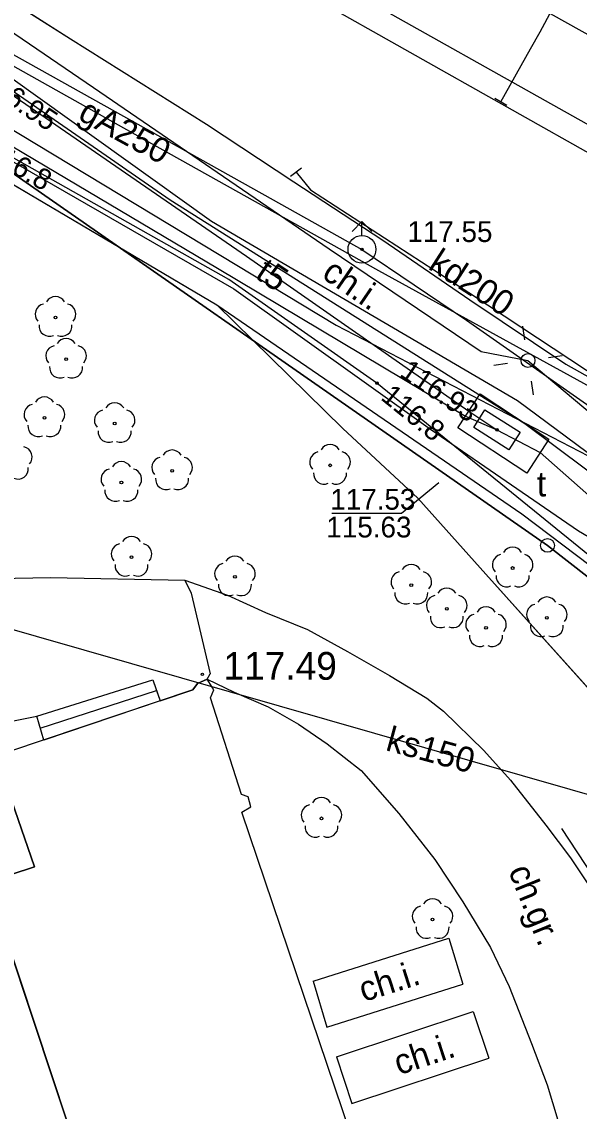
# Model space of a CAD drawing. Extents: x 6434771 to 6436222, y 5663454 to 5664782.
# Drawn here: x 6435031.8 to 6435051.9, y 5663965.39 to 5664004.67 of the extents above; entities that cross this region are included whole.
import ezdxf

# ---------------------------------------------------------------- set-up
doc = ezdxf.new("R2010")
doc.units = 0
for name, color, linetype in [('Warstwa 1', 7, 'Continuous'), ('Warstwa 10', 7, 'Continuous'), ('Warstwa 11', 7, 'Continuous'), ('Warstwa 12', 7, 'Continuous'), ('Warstwa 13', 7, 'Continuous'), ('Warstwa 14', 7, 'Continuous'), ('Warstwa 15', 7, 'Continuous'), ('Warstwa 2', 7, 'Continuous'), ('Warstwa 20', 7, 'Continuous'), ('Warstwa 25', 7, 'Continuous'), ('Warstwa 36', 7, 'Continuous'), ('Warstwa 37', 7, 'Continuous'), ('Warstwa 4', 7, 'Continuous'), ('Warstwa 5', 7, 'Continuous'), ('Warstwa 6', 7, 'Continuous'), ('Warstwa 7', 7, 'Continuous'), ('Warstwa 8', 7, 'Continuous'), ('Warstwa 9', 7, 'Continuous')]:
    doc.layers.add(name, color=color, linetype=linetype)

msp = doc.modelspace()

# ---------------------------------------------------------------- linework, layer by layer
at = {"layer": 'Warstwa 1'}
for p, q in [((6435026.957, 5664002.35), (6435050.759, 5663985.791)), ((6435026.957, 5664002.35), (6435050.759, 5663985.791)), ((6435050.759, 5663985.791), (6435055.831, 5663981.839)), ((6435050.759, 5663985.791), (6435055.831, 5663981.839))]:
    msp.add_line(p, q, dxfattribs=at)
for points in [[(6435045.895, 5663957.98), (6435039.739, 5663976.169), (6435040.058, 5663976.363), (6435039.962, 5663976.729), (6435039.728, 5663976.813), (6435038.605, 5663980.3), (6435038.722, 5663980.588), (6435038.493, 5663980.968), (6435038.135, 5663980.806), (6435037.976, 5663980.581), (6435031.321, 5663978.344)], [(6435030.834, 5663978.315), (6435032.261, 5663974.203), (6435030.566, 5663973.645), (6435039.149, 5663947.769)]]:
    msp.add_lwpolyline(points, dxfattribs=at)
at = {"layer": 'Warstwa 10'}
for points in [[(6434898.671, 5664074.419), (6434902.76, 5664072.365), (6434912.576, 5664067.627), (6434922.039, 5664062.843), (6434928.491, 5664059.745), (6434937.421, 5664055.317), (6434945.409, 5664050.998), (6434960.407, 5664042.783), (6434962.523, 5664038.882), (6434979.882, 5664029.167), (6434995.86, 5664020.139), (6435019.103, 5664006.754), (6435039.449, 5663995.035), (6435046.546, 5663989.977), (6435049.657, 5663987.84), (6435051.881, 5663986.317), (6435053.049, 5663985.633), (6435057.374, 5663981.038), (6435060.712, 5663977.517), (6435062.186, 5663975.788), (6435062.844, 5663975.005)], [(6434896.42, 5664071.06), (6434898.16, 5664073.03), (6434900.23, 5664072.06), (6434923.31, 5664061.23), (6434926.55, 5664059.81), (6434927.25, 5664060), (6434930.24, 5664058.57), (6434930.73, 5664057.88), (6434948.57, 5664048.49), (6434986.66, 5664027.63), (6435008.6, 5664015.27), (6435029.24, 5664003.72), (6435037.15, 5663998.25), (6435049.94, 5663990.19), (6435056.65, 5663985.18), (6435065.79, 5663976.31), (6435067.86, 5663972.11), (6435071.01, 5663962.36), (6435072.82, 5663959.6), (6435082.35, 5663954.64), (6435097.639, 5663946.244)], [(6435029.359, 5664004.111), (6435038.639, 5663997.479), (6435049.682, 5663991.014), (6435059.257, 5663983.908), (6435063.578, 5663979.846), (6435066.7, 5663975.848), (6435068.234, 5663972.039), (6435070.123, 5663963.685), (6435072.703, 5663960.364), (6435083.097, 5663954.788), (6435088.923, 5663951.177), (6435095.392, 5663948.519), (6435099.449, 5663946.22)], [(6435099.552, 5663946.221), (6435098.33, 5663946.9), (6435093.95, 5663949.47), (6435091.03, 5663950.32), (6435083.09, 5663955.03), (6435073.14, 5663960.81), (6435072.01, 5663961.77), (6435069.49, 5663965.07), (6435065.5, 5663971.7), (6435061.58, 5663976.4), (6435056.94, 5663981.63), (6435044.61, 5663991.64), (6435039.27, 5663995.38), (6435030.2, 5664000.49)]]:
    msp.add_lwpolyline(points, dxfattribs=at)
msp.add_circle((6435050.759, 5663985.791), 0.25, dxfattribs=at)
msp.add_circle((6435050.759, 5663985.791), 0.25, dxfattribs=at)
at = {"layer": 'Warstwa 11'}
for centre in [(6435033.018, 5663994.01), (6435033.4, 5663992.504), (6435032.618, 5663990.392), (6435035.152, 5663990.185), (6435037.222, 5663988.481), (6435042.919, 5663988.677), (6435035.393, 5663988.061), (6435035.76, 5663985.363), (6435049.503, 5663984.975), (6435039.489, 5663984.655), (6435045.848, 5663984.357), (6435047.128, 5663983.502), (6435048.543, 5663982.822), (6435050.737, 5663983.181), (6435042.609, 5663975.949), (6435046.615, 5663972.301)]:
    msp.add_circle(centre, 0.05, dxfattribs=at)
for centre, start, end in [((6435033.018, 5663994.385), 30.1471, 149.8529), ((6435032.661, 5663994.126), 102.1471, 221.8529), ((6435033.375, 5663994.126), 318.1471, 77.8529), ((6435032.798, 5663993.707), 174.1471, 293.8529), ((6435033.238, 5663993.707), 246.1471, 5.8529), ((6435033.4, 5663992.879), 30.1471, 149.8529), ((6435033.043, 5663992.62), 102.1471, 221.8529), ((6435033.757, 5663992.62), 318.1471, 77.8529), ((6435033.18, 5663992.201), 174.1471, 293.8529), ((6435033.62, 5663992.201), 246.1471, 5.8529), ((6435032.618, 5663990.767), 30.1471, 149.8529), ((6435032.261, 5663990.508), 102.1471, 221.8529), ((6435032.975, 5663990.508), 318.1471, 77.8529), ((6435035.152, 5663990.56), 30.1471, 149.8529), ((6435034.795, 5663990.301), 102.1471, 221.8529), ((6435035.509, 5663990.301), 318.1471, 77.8529), ((6435032.398, 5663990.089), 174.1471, 293.8529), ((6435032.838, 5663990.089), 246.1471, 5.8529), ((6435034.932, 5663989.882), 174.1471, 293.8529), ((6435035.372, 5663989.882), 246.1471, 5.8529), ((6435031.8, 5663988.976), 318.1471, 77.8529), ((6435037.222, 5663988.856), 30.1471, 149.8529), ((6435042.562, 5663988.793), 102.1471, 221.8529), ((6435042.919, 5663989.052), 30.1471, 149.8529), ((6435043.276, 5663988.793), 318.1471, 77.8529), ((6435035.393, 5663988.436), 30.1471, 149.8529), ((6435036.865, 5663988.597), 102.1471, 221.8529), ((6435037.579, 5663988.597), 318.1471, 77.8529), ((6435031.663, 5663988.557), 246.1471, 5.8529), ((6435035.036, 5663988.177), 102.1471, 221.8529), ((6435035.75, 5663988.177), 318.1471, 77.8529), ((6435042.699, 5663988.374), 174.1471, 293.8529), ((6435043.139, 5663988.374), 246.1471, 5.8529), ((6435037.002, 5663988.178), 174.1471, 293.8529), ((6435037.442, 5663988.178), 246.1471, 5.8529), ((6435035.173, 5663987.758), 174.1471, 293.8529), ((6435035.613, 5663987.758), 246.1471, 5.8529), ((6435035.76, 5663985.738), 30.1471, 149.8529), ((6435035.403, 5663985.479), 102.1471, 221.8529), ((6435036.117, 5663985.479), 318.1471, 77.8529), ((6435049.503, 5663985.35), 30.1471, 149.8529), ((6435039.489, 5663985.03), 30.1471, 149.8529), ((6435049.146, 5663985.091), 102.1471, 221.8529), ((6435049.86, 5663985.091), 318.1471, 77.8529), ((6435035.54, 5663985.06), 174.1471, 293.8529), ((6435035.98, 5663985.06), 246.1471, 5.8529), ((6435039.132, 5663984.771), 102.1471, 221.8529), ((6435039.846, 5663984.771), 318.1471, 77.8529), ((6435045.491, 5663984.473), 102.1471, 221.8529), ((6435045.848, 5663984.732), 30.1471, 149.8529), ((6435046.205, 5663984.473), 318.1471, 77.8529), ((6435049.283, 5663984.672), 174.1471, 293.8529), ((6435049.723, 5663984.672), 246.1471, 5.8529), ((6435039.269, 5663984.352), 174.1471, 293.8529), ((6435039.709, 5663984.352), 246.1471, 5.8529), ((6435045.628, 5663984.054), 174.1471, 293.8529), ((6435046.068, 5663984.054), 246.1471, 5.8529), ((6435047.128, 5663983.877), 30.1471, 149.8529), ((6435046.771, 5663983.618), 102.1471, 221.8529), ((6435047.485, 5663983.618), 318.1471, 77.8529), ((6435050.38, 5663983.297), 102.1471, 221.8529), ((6435050.737, 5663983.556), 30.1471, 149.8529), ((6435051.094, 5663983.297), 318.1471, 77.8529), ((6435048.186, 5663982.938), 102.1471, 221.8529), ((6435048.543, 5663983.197), 30.1471, 149.8529), ((6435048.9, 5663982.938), 318.1471, 77.8529), ((6435046.908, 5663983.199), 174.1471, 293.8529), ((6435047.348, 5663983.199), 246.1471, 5.8529), ((6435050.517, 5663982.878), 174.1471, 293.8529), ((6435050.957, 5663982.878), 246.1471, 5.8529), ((6435048.323, 5663982.519), 174.1471, 293.8529), ((6435048.763, 5663982.519), 246.1471, 5.8529), ((6435042.609, 5663976.324), 30.1471, 149.8529), ((6435042.252, 5663976.065), 102.1471, 221.8529), ((6435042.966, 5663976.065), 318.1471, 77.8529), ((6435042.389, 5663975.646), 174.1471, 293.8529), ((6435042.829, 5663975.646), 246.1471, 5.8529), ((6435046.615, 5663972.676), 30.1471, 149.8529), ((6435046.258, 5663972.417), 102.1471, 221.8529), ((6435046.972, 5663972.417), 318.1471, 77.8529), ((6435046.395, 5663971.998), 174.1471, 293.8529), ((6435046.835, 5663971.998), 246.1471, 5.8529)]:
    msp.add_arc(centre, 0.375, start, end, dxfattribs=at)
at = {"layer": 'Warstwa 12'}
for points in [[(6434879.158, 5664078.856), (6434884.466, 5664077.041), (6434884.943, 5664076.892), (6434885.361, 5664076.61), (6434904.643, 5664068.316), (6434925.269, 5664058.705), (6434945.05, 5664048.685), (6434974.567, 5664032.476), (6434974.989, 5664032.261), (6434975.127, 5664032.48), (6434976.891, 5664035.328), (6434977.019, 5664035.547), (6434977.471, 5664035.311), (6435021.423, 5664010.318), (6435021.865, 5664010.097), (6435021.856, 5664009.772), (6435020.661, 5664007.687), (6435020.508, 5664007.434), (6435020.935, 5664007.143), (6435043.134, 5663993.734), (6435056.442, 5663986.832), (6435065.286, 5663979.645), (6435065.567, 5663979.291)], [(6435076.981, 5663977.987), (6435060.8, 5663986.83), (6435044.672, 5663995.689), (6435035.779, 5664000.664), (6435026.559, 5664005.848), (6435021.216, 5664008.862), (6435015.543, 5664011.986), (6435005.727, 5664017.515), (6434993.895, 5664024.292), (6434988.15, 5664027.391), (6434986.652, 5664028.144), (6434985.953, 5664028.56), (6434978.495, 5664032.512), (6434971.253, 5664036.441), (6434966.665, 5664038.927), (6434949.941, 5664048.002), (6434948.145, 5664048.942), (6434947.222, 5664049.507), (6434943.986, 5664051.256), (6434934.8, 5664055.982), (6434925.516, 5664060.59), (6434905.925, 5664069.826), (6434896.606, 5664074.336), (6434894.752, 5664075.227)], [(6434928.096, 5664058.264), (6434929.076, 5664057.604), (6434939.486, 5664051.98), (6434948.125, 5664047.34), (6434952.325, 5664045.068), (6434966.421, 5664037.465), (6434988.007, 5664025.883), (6434989.76, 5664024.876), (6434992.028, 5664023.706), (6434998.449, 5664019.821), (6435020.142, 5664006.907), (6435038.86, 5663995.783), (6435047.805, 5663990.452), (6435048.936, 5663989.958)], [(6434986.93, 5664031.717), (6434992.77, 5664028.437), (6435004.492, 5664021.894), (6435005.105, 5664018.185), (6435011.542, 5664014.684), (6435027.829, 5664005.549), (6435040.87, 5663998.248), (6435044.067, 5663996.463), (6435047.835, 5663993.916), (6435060.611, 5663984.964), (6435069.684, 5663978.472), (6435072.37, 5663972.912), (6435073.728, 5663967.815), (6435073.844, 5663967.084), (6435073.839, 5663962.379), (6435073.912, 5663958.232), (6435075.469, 5663957.501), (6435076.211, 5663957.1), (6435093.406, 5663947.233)], [(6434990.077, 5664025.283), (6434990.843, 5664024.793), (6434996.581, 5664021.557), (6435010.751, 5664013.657), (6435028.787, 5664003.637), (6435029.346, 5664003.299), (6435029.924, 5664003.079), (6435039.903, 5663996.215), (6435047.922, 5663990.632), (6435048.936, 5663989.958)], [(6435029.763, 5664005.454), (6435034.388, 5664002.299), (6435042.886, 5663996.481), (6435048.366, 5663992.784), (6435050.056, 5663992.458), (6435053.785, 5663989.318), (6435060.963, 5663983.658), (6435062.158, 5663982.516), (6435067.739, 5663976.436), (6435069.698, 5663972.561), (6435070.863, 5663972.195), (6435071.455, 5663970.037), (6435072.977, 5663964.049), (6435072.957, 5663962.572), (6435082.449, 5663958.039), (6435089.417, 5663954.626), (6435090.354, 5663954.835), (6435092.145, 5663953.831), (6435102.441, 5663948.316), (6435106.279, 5663946.137)], [(6435048.936, 5663989.958), (6435050.494, 5663989.135), (6435059.853, 5663980.868), (6435060.69, 5663980.006)]]:
    msp.add_lwpolyline(points, dxfattribs=at)
at = {"layer": 'Warstwa 14'}
msp.add_lwpolyline([(6435042.984, 5663986.953), (6435045.497, 5663986.953), (6435046.843, 5663988.054)], dxfattribs=at)
for centre in [(6435044.61, 5663991.64), (6435048.936, 5663989.958), (6435048.936, 5663989.958)]:
    msp.add_circle(centre, 0.045, dxfattribs=at)
at = {"layer": 'Warstwa 15'}
msp.add_lwpolyline([(6435047.527, 5663990.027), (6435048.327, 5663991.25), (6435050.813, 5663989.623), (6435050.013, 5663988.4)], close=True, dxfattribs=at)
at = {"layer": 'Warstwa 2'}
for points in [[(6434997.74, 5664018.73), (6434999.49, 5664017.72), (6435038.83, 5663994.46)], [(6435038.83, 5663994.46), (6435043.374, 5663990.006), (6435046.081, 5663987.498), (6435048.536, 5663984.758)], [(6435072.736, 5663952.323), (6435067.928, 5663955.002), (6435067.798, 5663959.143), (6435063.036, 5663968.152), (6435059.834, 5663972.111), (6435056.391, 5663976.002), (6435048.536, 5663984.758)], [(6435031.791, 5663948.063), (6435032.526, 5663945.742), (6435032.791, 5663945.495), (6435036.28, 5663946.559), (6435036.993, 5663946.976), (6435039.149, 5663947.769), (6435035.704, 5663958.157), (6435033.205, 5663965.69), (6435031.909, 5663969.598), (6435030.566, 5663973.645), (6435032.261, 5663974.203), (6435030.834, 5663978.315)]]:
    msp.add_lwpolyline(points, dxfattribs=at)
msp.add_circle((6435050.056, 5663992.458), 0.25, dxfattribs=at)
at = {"layer": 'Warstwa 20'}
for p, q in [((6435049.288, 5664001.652), (6435048.856, 5664001.902)), ((6435041.493, 5663999.098), (6435041.889, 5663999.404))]:
    msp.add_line(p, q, dxfattribs=at)
at = {"layer": 'Warstwa 25'}
msp.add_circle((6435038.314, 5663981.14), 0.045, dxfattribs=at)
at = {"layer": 'Warstwa 36'}
msp.add_line((6435032.47, 5663979.205), (6435036.664, 5663980.564), dxfattribs=at)
msp.add_lwpolyline([(6435032.592, 5663978.772), (6435032.35, 5663979.64), (6435036.531, 5663980.942), (6435036.798, 5663980.185)], close=True, dxfattribs=at)
at = {"layer": 'Warstwa 37'}
for points in [[(6434960.077, 5664056.173), (6434990.448, 5664038.674), (6435077.587, 5663990.05), (6435102.909, 5663975.479)], [(6435101.756, 5663972.773), (6435075.965, 5663987.638), (6434996.783, 5664032.063), (6434958.785, 5664053.528)]]:
    msp.add_lwpolyline(points, dxfattribs=at)
at = {"layer": 'Warstwa 4'}
for points in [[(6435043.713, 5663997.109), (6435044.067, 5663997.463)], [(6435044.421, 5663997.109), (6435044.067, 5663997.463)], [(6435044.067, 5663996.963), (6435044.067, 5663997.463)], [(6435049.945, 5663993.2), (6435049.872, 5663993.694)], [(6435049.314, 5663992.347), (6435048.82, 5663992.274)], [(6435050.798, 5663992.569), (6435051.292, 5663992.642)], [(6435050.167, 5663991.716), (6435050.24, 5663991.222)], [(6435061.004, 5663948.939), (6435060.419, 5663957.687), (6435058.856, 5663963.156), (6435055.243, 5663969.55), (6435051.275, 5663975.588)]]:
    msp.add_lwpolyline(points, dxfattribs=at)
msp.add_lwpolyline([(6435048.102, 5663990.043), (6435048.504, 5663990.677), (6435049.77, 5663989.873), (6435049.368, 5663989.239)], close=True, dxfattribs=at)
msp.add_circle((6435044.067, 5663996.463), 0.5, dxfattribs=at)
at = {"layer": 'Warstwa 5'}
for p, q in [((6434999.49, 5664017.72), (6435038.83, 5663994.46)), ((6435038.83, 5663994.46), (6435043.374, 5663990.006)), ((6435038.83, 5663994.46), (6435049.833, 5663986.932)), ((6435038.83, 5663994.46), (6435043.374, 5663990.006)), ((6435043.374, 5663990.006), (6435046.081, 5663987.498)), ((6435043.374, 5663990.006), (6435046.081, 5663987.498)), ((6435046.081, 5663987.498), (6435048.536, 5663984.758)), ((6435046.081, 5663987.498), (6435048.536, 5663984.758)), ((6435049.833, 5663986.932), (6435053.836, 5663983.904)), ((6435030.14, 5663984.577), (6435032.835, 5663984.632)), ((6435032.835, 5663984.632), (6435037.682, 5663984.542)), ((6435037.682, 5663984.542), (6435039.218, 5663983.992)), ((6435048.536, 5663984.758), (6435056.391, 5663976.002)), ((6435048.536, 5663984.758), (6435056.391, 5663976.002)), ((6435039.218, 5663983.992), (6435040.596, 5663983.376)), ((6435040.596, 5663983.376), (6435042.108, 5663982.759)), ((6435042.108, 5663982.759), (6435043.551, 5663981.964)), ((6435043.551, 5663981.964), (6435045.061, 5663981.103)), ((6435045.061, 5663981.103), (6435046.414, 5663980.287)), ((6435046.414, 5663980.287), (6435047.011, 5663979.814)), ((6435047.011, 5663979.814), (6435048.458, 5663978.4)), ((6435048.458, 5663978.4), (6435049.428, 5663977.322)), ((6435049.428, 5663977.322), (6435050.705, 5663975.709)), ((6435050.705, 5663975.709), (6435051.584, 5663974.523)), ((6435051.584, 5663974.523), (6435053.067, 5663972.307))]:
    msp.add_line(p, q, dxfattribs=at)
at = {"layer": 'Warstwa 6'}
for points in [[(6435199.169, 5663878.85), (6435069.683, 5663952.11), (6435070.435, 5663958.091), (6435069.483, 5663961.233), (6435068.325, 5663963.837), (6435062.043, 5663974.514), (6435058.095, 5663979.622), (6435055.831, 5663981.839), (6435050.759, 5663985.791), (6435026.957, 5664002.35), (6434999.334, 5664017.996), (6434991.09, 5664022.666), (6434980.58, 5664028.593), (6434951.952, 5664044.671), (6434942.859, 5664049.431), (6434933.864, 5664054.041), (6434925.132, 5664058.117), (6434918.181, 5664061.441), (6434909.328, 5664065.359), (6434902.911, 5664068.147), (6434896.533, 5664070.874)], [(6435027.108, 5664008.168), (6435033.554, 5664004.049), (6435038.461, 5664000.982), (6435041.615, 5663998.897), (6435044.819, 5663996.801), (6435047.954, 5663994.645), (6435051.422, 5663992.324), (6435054.269, 5663990.729)]]:
    msp.add_lwpolyline(points, dxfattribs=at)
msp.add_lwpolyline([(6435026.957, 5664002.35), (6435050.759, 5663985.791), (6435055.831, 5663981.839), (6435058.095, 5663979.622), (6435062.043, 5663974.514), (6435068.325, 5663963.837), (6435069.483, 5663961.233), (6435070.435, 5663958.091), (6435069.683, 5663952.11), (6435120.043, 5663983.972), (6435070.884, 5664005.038), (6435011.285, 5664038.642), (6434957.736, 5664068.872), (6434942.859, 5664049.431), (6434951.952, 5664044.671), (6434980.58, 5664028.593), (6434991.09, 5664022.666), (6434999.334, 5664017.996)], close=True, dxfattribs=at)
for centre in [(6435044.067, 5663996.463), (6435048.936, 5663989.958)]:
    msp.add_circle(centre, 0.045, dxfattribs=at)
at = {"layer": 'Warstwa 7'}
for points in [[(6434960.516, 5664035.877), (6434960.352, 5664035.549), (6434973.215, 5664023.743), (6434973.286, 5664023.312), (6434995.263, 5664004.719), (6434995.671, 5664004.448), (6435025.261, 5663984.54), (6435077.854, 5663969.472)], [(6435049.072, 5664001.777), (6435050.141, 5664003.69), (6435050.499, 5664004.312), (6435051.281, 5664005.776), (6435051.511, 5664006.218), (6435055.779, 5664004.771), (6435056.167, 5664004.607), (6435056.821, 5664004.929), (6435057.95, 5664005.645), (6435058.494, 5664005.989)], [(6435041.691, 5663999.251), (6435042.211, 5663998.615), (6435047.994, 5663994.861), (6435058.743, 5663987.769), (6435059.445, 5663987.461), (6435061.77, 5663989.977), (6435070.529, 5663999.495)]]:
    msp.add_lwpolyline(points, dxfattribs=at)
at = {"layer": 'Warstwa 8'}
for p, q in [((6434997.36, 5664030.89), (6435055.68, 5663998)), ((6434997.36, 5664030.89), (6435055.68, 5663998)), ((6435027.108, 5664008.168), (6435033.554, 5664004.049)), ((6435033.554, 5664004.049), (6435038.461, 5664000.982)), ((6435038.461, 5664000.982), (6435041.615, 5663998.897)), ((6435041.615, 5663998.897), (6435044.819, 5663996.801)), ((6435044.819, 5663996.801), (6435047.954, 5663994.645)), ((6435047.954, 5663994.645), (6435051.422, 5663992.324)), ((6435051.422, 5663992.324), (6435054.269, 5663990.729)), ((6435030.14, 5663984.577), (6435032.835, 5663984.632)), ((6435032.835, 5663984.632), (6435037.682, 5663984.542)), ((6435037.682, 5663984.542), (6435037.915, 5663984.063)), ((6435037.915, 5663984.063), (6435038.359, 5663982.177)), ((6435038.359, 5663982.177), (6435038.592, 5663981.158)), ((6435032.35, 5663979.64), (6435036.531, 5663980.942)), ((6435036.531, 5663980.942), (6435036.664, 5663980.564)), ((6435038.135, 5663980.806), (6435038.493, 5663980.968)), ((6435038.493, 5663980.968), (6435038.592, 5663981.158)), ((6435036.664, 5663980.564), (6435036.798, 5663980.185)), ((6435036.798, 5663980.185), (6435037.976, 5663980.581)), ((6435037.976, 5663980.581), (6435038.135, 5663980.806)), ((6435031.447, 5663979.454), (6435032.35, 5663979.64))]:
    msp.add_line(p, q, dxfattribs=at)
at = {"layer": 'Warstwa 9'}
for p, q in [((6434999.49, 5664017.72), (6435038.83, 5663994.46)), ((6435027.108, 5664008.168), (6435033.554, 5664004.049)), ((6435033.554, 5664004.049), (6435038.461, 5664000.982)), ((6435038.461, 5664000.982), (6435041.615, 5663998.897)), ((6435041.615, 5663998.897), (6435044.819, 5663996.801)), ((6435044.819, 5663996.801), (6435047.954, 5663994.645)), ((6435038.83, 5663994.46), (6435049.833, 5663986.932)), ((6435047.954, 5663994.645), (6435051.422, 5663992.324)), ((6435051.422, 5663992.324), (6435054.269, 5663990.729)), ((6435049.833, 5663986.932), (6435053.836, 5663983.904)), ((6435037.682, 5663984.542), (6435039.218, 5663983.992)), ((6435037.682, 5663984.542), (6435037.915, 5663984.063)), ((6435037.915, 5663984.063), (6435038.359, 5663982.177)), ((6435039.218, 5663983.992), (6435040.596, 5663983.376)), ((6435040.596, 5663983.376), (6435042.108, 5663982.759)), ((6435042.108, 5663982.759), (6435043.551, 5663981.964)), ((6435038.359, 5663982.177), (6435038.592, 5663981.158)), ((6435043.551, 5663981.964), (6435045.061, 5663981.103)), ((6435038.493, 5663980.968), (6435038.592, 5663981.158)), ((6435038.493, 5663980.968), (6435039.466, 5663980.501)), ((6435045.061, 5663981.103), (6435046.414, 5663980.287)), ((6435039.466, 5663980.501), (6435040.688, 5663979.976)), ((6435046.414, 5663980.287), (6435047.011, 5663979.814)), ((6435040.688, 5663979.976), (6435041.776, 5663979.341)), ((6435047.011, 5663979.814), (6435048.458, 5663978.4)), ((6435041.776, 5663979.341), (6435042.817, 5663978.64)), ((6435042.817, 5663978.64), (6435044.035, 5663977.671)), ((6435048.458, 5663978.4), (6435049.428, 5663977.322)), ((6435044.035, 5663977.671), (6435045.402, 5663976.123)), ((6435049.428, 5663977.322), (6435050.705, 5663975.709)), ((6435045.402, 5663976.123), (6435046.7, 5663974.466)), ((6435050.705, 5663975.709), (6435051.584, 5663974.523)), ((6435046.7, 5663974.466), (6435047.71, 5663972.944)), ((6435051.584, 5663974.523), (6435053.067, 5663972.307)), ((6435047.71, 5663972.944), (6435048.706, 5663971.291)), ((6435042.308, 5663970.083), (6435047.207, 5663971.633)), ((6435047.207, 5663971.633), (6435047.707, 5663969.977)), ((6435048.706, 5663971.291), (6435049.382, 5663969.885)), ((6435042.308, 5663970.083), (6435042.808, 5663968.426)), ((6435042.808, 5663968.426), (6435047.707, 5663969.977)), ((6435049.382, 5663969.885), (6435050.184, 5663967.834)), ((6435043.145, 5663967.352), (6435048.075, 5663968.983)), ((6435048.075, 5663968.983), (6435048.645, 5663967.306)), ((6435050.184, 5663967.834), (6435050.747, 5663966.34)), ((6435043.145, 5663967.352), (6435043.705, 5663965.675)), ((6435043.705, 5663965.675), (6435048.645, 5663967.306)), ((6435050.747, 5663966.34), (6435051.134, 5663965.07))]:
    msp.add_line(p, q, dxfattribs=at)

# ---------------------------------------------------------------- texts
at = {"layer": 'Warstwa 13'}
for s, rotation, p in [('gA250', 331.5019, (6435033.786, 5664001.166)), ('t5', 326.1677, (6435040.176, 5663995.459))]:
    msp.add_text(s, height=0.9, rotation=rotation, dxfattribs=at).set_placement(p)
at = {"layer": 'Warstwa 14'}
for s, rotation, p in [('116.95', 326.1677, (6435030.215, 5664002.405)), ('116.8', 330.0581, (6435030.425, 5663999.8)), ('116.93', 325.8468, (6435045.392, 5663991.919)), ('116.8', 320.9308, (6435044.709, 5663991.076))]:
    msp.add_text(s, height=0.75, rotation=rotation, dxfattribs=at).set_placement(p)
msp.add_text('115.63', height=0.75, dxfattribs=at).set_placement((6435042.786, 5663986.078))
at = {"layer": 'Warstwa 25'}
msp.add_text('117.49', height=1, dxfattribs=at).set_placement((6435039.075, 5663980.947))
at = {"layer": 'Warstwa 5'}
msp.add_text('t', height=0.9, dxfattribs=at).set_placement((6435050.376, 5663987.557))
at = {"layer": 'Warstwa 6'}
for s, p in [('117.55', (6435045.707, 5663996.729)), ('117.53', (6435042.928, 5663987.078))]:
    msp.add_text(s, height=0.75, dxfattribs=at).set_placement(p)
at = {"layer": 'Warstwa 7'}
for s, rotation, p in [('kd200', 327.2735, (6435046.417, 5663995.784)), ('ks150', 344.7086, (6435044.887, 5663978.413))]:
    msp.add_text(s, height=0.9, rotation=rotation, dxfattribs=at).set_placement(p)
at = {"layer": 'Warstwa 9'}
for s, rotation, p in [('ch.i.', 325.6234, (6435042.576, 5663995.465)), ('ch.gr.', 292.0595, (6435049.335, 5663974.064)), ('ch.i.', 17.5669, (6435044.13, 5663969.323)), ('ch.i.', 18.2716, (6435045.402, 5663966.684))]:
    msp.add_text(s, height=0.9, rotation=rotation, dxfattribs=at).set_placement(p)

doc.saveas('drawing.dxf')
